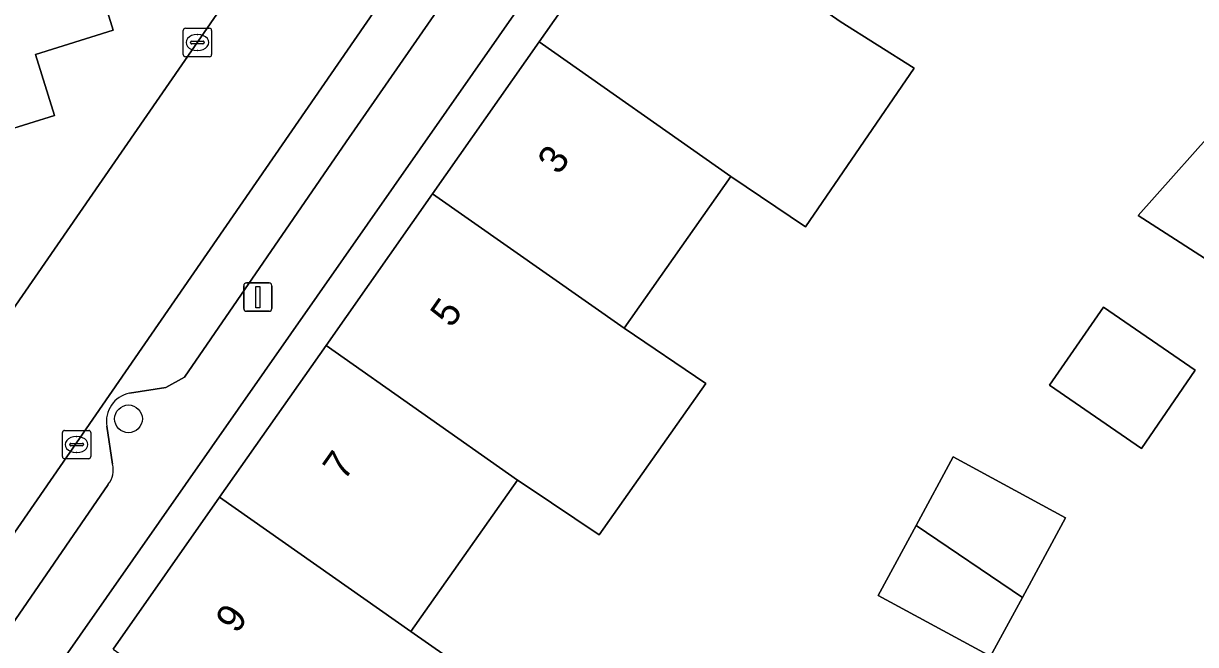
# Model space of a CAD drawing. Extents: x 161798 to 162385, y 382315 to 382833.
# Drawn here: x 161957.55 to 161998.86, y 382715.1 to 382737 of the extents above; entities that cross this region are included whole.
import ezdxf

# ---------------------------------------------------------------- set-up
doc = ezdxf.new("R2010")
doc.units = 0
for name, color, linetype in [('IMGEO_Boom', 7, 'Continuous'), ('IMGEO_Erf', 7, 'Continuous'), ('IMGEO_Kolk', 7, 'Continuous'), ('IMGEO_Lichtmast', 7, 'Continuous'), ('IMGEO_Pand', 7, 'Continuous'), ('IMGEO_Pand_nummerreeks', 7, 'Continuous'), ('IMGEO_Parkeervlak_open', 7, 'Continuous'), ('IMGEO_Rijbaan_lokaal_open', 7, 'Continuous'), ('IMGEO_Voetpad_open', 7, 'Continuous')]:
    doc.layers.add(name, color=color, linetype=linetype)

msp = doc.modelspace()

# ---------------------------------------------------------------- linework, layer by layer
at = {"layer": 'IMGEO_Boom'}
msp.add_circle((161961.254, 382723.06), 0.489, dxfattribs=at)
at = {"layer": 'IMGEO_Erf'}
for points in [[(162000, 382748.49), (161998.309, 382750), (161995.84, 382752.203), (161995.75, 382752.284), (161993.712, 382750), (161991.488, 382747.507), (161991.557, 382747.445), (161997.283, 382742.337), (161993.653, 382738.267), (161987.136, 382742.39), (161987.064, 382742.454), (161985.478, 382743.87), (161981.747, 382747.198), (161955.826, 382710.123)], [(161960.71, 382714.946), (161964.465, 382720.297), (161968.22, 382725.647), (161971.974, 382730.996), (161975.729, 382736.346), (161979.571, 382741.821), (161983.664, 382738.949), (161986.339, 382737.072), (161988.941, 382735.417), (161985.112, 382729.835), (161982.489, 382731.601), (161978.728, 382726.255), (161981.603, 382724.304), (161977.848, 382718.967), (161975.308, 382720.671), (161974.962, 382720.903), (161971.206, 382715.565), (161973.691, 382713.821)], [(162000, 382728.195), (161996.847, 382730.23), (162000, 382733.772)]]:
    msp.add_lwpolyline(points, dxfattribs=at)
for points in [[(161998.854, 382724.777), (161996.958, 382722.018), (161993.72, 382724.242), (161995.616, 382727.001)], [(161989.014, 382719.297), (161990.323, 382721.718), (161994.281, 382719.576), (161992.761, 382716.766), (161991.637, 382714.69), (161991.568, 382714.727), (161991.388, 382714.824), (161987.679, 382716.831), (161987.749, 382716.961)]]:
    msp.add_lwpolyline(points, close=True, dxfattribs=at)
at = {"layer": 'IMGEO_Kolk'}
for p, q in [((161963.184, 382735.901), (161963.184, 382736.753)), ((161963.259, 382736.827), (161964.111, 382736.827)), ((161963.672, 382736.607), (161963.697, 382736.607)), ((161964.185, 382736.753), (161964.185, 382735.901)), ((161963.443, 382736.321), (161963.443, 382736.333)), ((161963.881, 382736.284), (161963.483, 382736.284)), ((161963.486, 382736.37), (161963.884, 382736.37)), ((161963.927, 382736.333), (161963.927, 382736.321)), ((161964.111, 382735.827), (161963.259, 382735.827)), ((161963.695, 382736.047), (161963.67, 382736.047)), ((161958.924, 382721.728), (161958.924, 382722.58)), ((161958.999, 382722.654), (161959.851, 382722.654)), ((161959.925, 382722.58), (161959.925, 382721.728)), ((161959.183, 382722.148), (161959.183, 382722.16)), ((161959.621, 382722.111), (161959.223, 382722.111)), ((161959.226, 382722.197), (161959.624, 382722.197)), ((161959.412, 382722.434), (161959.437, 382722.434)), ((161959.667, 382722.16), (161959.667, 382722.148)), ((161959.435, 382721.874), (161959.41, 382721.874)), ((161959.851, 382721.654), (161958.999, 382721.654))]:
    msp.add_line(p, q, dxfattribs=at)
for points in [[(161963.184, 382735.901), (161963.184, 382736.753)], [(161963.259, 382736.827), (161964.111, 382736.827)], [(161964.185, 382736.753), (161964.185, 382735.901)], [(161964.111, 382735.827), (161963.259, 382735.827)], [(161958.924, 382721.728), (161958.924, 382722.58)], [(161958.999, 382722.654), (161959.851, 382722.654)], [(161959.925, 382722.58), (161959.925, 382721.728)], [(161959.851, 382721.654), (161958.999, 382721.654)]]:
    msp.add_lwpolyline(points, dxfattribs=at)
for centre, radius, start, end in [((161963.261, 382736.751), 0.0765, 91.552, 178.448), ((161963.261, 382736.751), 0.0765, 91.552, 178.448), ((161964.109, 382736.751), 0.0765, 1.552, 88.448), ((161964.109, 382736.751), 0.0765, 1.552, 88.448), ((161963.483, 382736.33), 0.0403, 85.8775, 175.7526), ((161963.48, 382736.32), 0.0366, 178.938, 274.7102), ((161963.884, 382736.327), 0.043, 264.8664, 352.4533), ((161963.888, 382736.332), 0.0386, 1.7309, 96.639), ((161963.261, 382735.903), 0.0765, 181.552, 268.448), ((161963.261, 382735.903), 0.0765, 181.552, 268.448), ((161964.109, 382735.903), 0.0765, 271.552, 358.448), ((161964.109, 382735.903), 0.0765, 271.552, 358.448), ((161959.001, 382722.578), 0.0765, 91.552, 178.448), ((161959.001, 382722.578), 0.0765, 91.552, 178.448), ((161959.849, 382722.578), 0.0765, 1.552, 88.448), ((161959.849, 382722.578), 0.0765, 1.552, 88.448), ((161959.223, 382722.157), 0.0403, 85.8775, 175.7526), ((161959.22, 382722.147), 0.0366, 178.938, 274.7102), ((161959.624, 382722.154), 0.043, 264.8664, 352.4533), ((161959.628, 382722.159), 0.0386, 1.7309, 96.639), ((161959.001, 382721.73), 0.0765, 181.552, 268.448), ((161959.001, 382721.73), 0.0765, 181.552, 268.448), ((161959.849, 382721.73), 0.0765, 271.552, 358.448), ((161959.849, 382721.73), 0.0765, 271.552, 358.448)]:
    msp.add_arc(centre, radius, start, end, dxfattribs=at)
for centre, major_axis, ratio, start_param, end_param in [((161963.671, 382736.327), (-0.387, 0.002), 0.722429, 4.712389, 7.853982), ((161963.696, 382736.327), (-0.39, 0.002), 0.717154, 1.570796, 4.712389), ((161959.411, 382722.154), (-0.387, 0.002), 0.722429, 4.712389, 7.853982), ((161959.436, 382722.154), (-0.39, 0.002), 0.717154, 1.570796, 4.712389)]:
    msp.add_ellipse(centre, major_axis=major_axis, ratio=ratio, start_param=start_param, end_param=end_param, dxfattribs=at)
at = {"layer": 'IMGEO_Lichtmast'}
for p, q in [((161965.317, 382726.952), (161965.317, 382727.752)), ((161965.317, 382727.752), (161965.317, 382726.952)), ((161965.417, 382727.852), (161966.207, 382727.852)), ((161966.207, 382727.852), (161965.417, 382727.852)), ((161966.307, 382727.752), (161966.307, 382726.952)), ((161966.307, 382726.952), (161966.307, 382727.752)), ((161966.207, 382726.852), (161965.417, 382726.852)), ((161965.417, 382726.852), (161966.207, 382726.852))]:
    msp.add_line(p, q, dxfattribs=at)
msp.add_lwpolyline([(161965.737, 382727.727), (161965.887, 382727.727), (161965.887, 382726.977), (161965.737, 382726.977), (161965.737, 382727.727)], dxfattribs=at)
for centre, start, end in [((161965.417, 382727.752), 90, 180), ((161965.417, 382727.752), 90, 180), ((161966.207, 382727.752), 0, 90), ((161966.207, 382727.752), 360, 90), ((161965.417, 382726.952), 180, 270), ((161965.417, 382726.952), 180, 270), ((161966.207, 382726.952), 270, 0), ((161966.207, 382726.952), 270, 0)]:
    msp.add_arc(centre, 0.1, start, end, dxfattribs=at)
at = {"layer": 'IMGEO_Pand'}
for points in [[(162022.858, 382743.945), (162017.324, 382748.986), (162016.083, 382750.117), (162015.335, 382750.798), (162014.601, 382750), (162005.499, 382739.95), (162004.032, 382738.302), (162000, 382733.772), (161996.847, 382730.23), (162000, 382728.195), (162005.49, 382724.651)], [(161983.664, 382738.949), (161979.571, 382741.821), (161975.729, 382736.346), (161982.489, 382731.601), (161985.112, 382729.835), (161988.941, 382735.417), (161986.339, 382737.072)], [(161975.729, 382736.346), (161971.974, 382730.996), (161978.728, 382726.255), (161982.489, 382731.601)], [(161971.974, 382730.996), (161968.22, 382725.647), (161974.962, 382720.903), (161975.308, 382720.671), (161977.848, 382718.967), (161981.603, 382724.304), (161978.728, 382726.255)], [(161998.854, 382724.777), (161995.616, 382727.001), (161993.72, 382724.242), (161996.958, 382722.018)], [(161974.962, 382720.903), (161968.22, 382725.647), (161964.465, 382720.297), (161971.206, 382715.565)], [(161989.014, 382719.297), (161992.761, 382716.766), (161994.281, 382719.576), (161990.323, 382721.718)], [(161971.206, 382715.565), (161964.465, 382720.297), (161960.71, 382714.946), (161967.445, 382710.219), (161968.888, 382712.27), (161971.373, 382710.526), (161973.691, 382713.821)], [(161989.014, 382719.297), (161987.749, 382716.961), (161987.679, 382716.831), (161991.388, 382714.824), (161991.568, 382714.727), (161991.637, 382714.69), (161992.761, 382716.766)]]:
    msp.add_lwpolyline(points, close=True, dxfattribs=at)
at = {"layer": 'IMGEO_Parkeervlak_open'}
for points in [[(161950.871, 382717.792), (161974.155, 382751.509), (161975.168, 382752.813), (161968.392, 382750.903), (161968.649, 382750), (161969.029, 382748.71), (161966.314, 382747.929), (161966.947, 382745.726), (161964.207, 382744.9), (161964.866, 382742.715), (161962.14, 382741.911), (161962.784, 382739.751), (161960.061, 382738.905), (161960.71, 382736.757), (161957.979, 382735.907), (161958.647, 382733.757), (161955.922, 382732.912)], [(161974.497, 382744.072), (161954.232, 382714.711)], [(161961.29, 382723.965), (161962.572, 382724.162), (161963.223, 382724.527), (161968.922, 382732.829), (161974.494, 382740.858)], [(161960.696, 382721.466), (161960.49, 382722.799)], [(161955.188, 382715.124), (161956.513, 382715.352), (161957.145, 382715.801), (161960.54, 382720.752)]]:
    msp.add_lwpolyline(points, dxfattribs=at)
for centre, radius, start, end in [((161961.492, 382722.969), 1.016, 101.463, 189.6284), ((161959.863, 382721.274), 0.855, 322.3806, 12.97)]:
    msp.add_arc(centre, radius, start, end, dxfattribs=at)
at = {"layer": 'IMGEO_Rijbaan_lokaal_open'}
msp.add_lwpolyline([(161953.014, 382713.254), (161953.841, 382714.33), (161954.011, 382714.515), (161954.232, 382714.711), (161974.497, 382744.072), (161975.012, 382744.815), (161978.57, 382749.833), (161978.687, 382750), (161978.946, 382750.365), (161982.788, 382755.905), (161991.783, 382769.02), (161988.335, 382771.671), (161988.086, 382771.315), (161983.272, 382764.558), (161979.867, 382759.641), (161975.168, 382752.813), (161974.155, 382751.509), (161950.871, 382717.792)], dxfattribs=at)
at = {"layer": 'IMGEO_Voetpad_open'}
for points in [[(161955.922, 382732.912), (161958.647, 382733.757), (161957.979, 382735.907), (161960.71, 382736.757), (161960.061, 382738.905), (161962.784, 382739.751), (161962.14, 382741.911), (161964.866, 382742.715), (161964.207, 382744.9), (161966.947, 382745.726), (161966.314, 382747.929), (161969.029, 382748.71), (161968.649, 382750), (161968.392, 382750.903), (161975.168, 382752.813), (161974.785, 382753.021), (161979.484, 382759.903), (161979.867, 382759.641), (161980.007, 382760.209), (161979.541, 382761.728), (161979.734, 382762.486), (161981.502, 382765.002), (161984.882, 382769.995)], [(161953.212, 382706.879), (161955.826, 382710.123), (161981.747, 382747.198), (161984.249, 382750), (161997.519, 382764.558), (161991.848, 382768.97), (161991.783, 382769.02)], [(161974.494, 382740.858), (161968.922, 382732.829), (161963.223, 382724.527), (161962.572, 382724.162), (161961.29, 382723.965)], [(161960.49, 382722.799), (161960.696, 382721.466)], [(161960.54, 382720.752), (161957.145, 382715.801), (161956.513, 382715.352), (161955.188, 382715.124)]]:
    msp.add_lwpolyline(points, dxfattribs=at)
for centre, radius, start, end in [((161961.492, 382722.969), 1.016, 101.463, 189.6284), ((161959.863, 382721.274), 0.855, 322.3806, 12.97)]:
    msp.add_arc(centre, radius, start, end, dxfattribs=at)

# ---------------------------------------------------------------- texts
at = {"layer": 'IMGEO_Pand_nummerreeks'}
for s, rotation, p in [('3', 54.9381, (161976.422, 382731.625)), ('5', 54.9381, (161972.639, 382726.234)), ('7', 54.9381, (161968.855, 382720.843)), ('9', 54.9409, (161965.072, 382715.453))]:
    msp.add_text(s, height=1, rotation=rotation, dxfattribs=at).set_placement(p)

doc.saveas('drawing.dxf')
